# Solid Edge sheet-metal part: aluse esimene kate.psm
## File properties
Title: aluse esimene kate
Author: Stella-Marii
Template: Iso Metric Sheet Metal.psm
Last saved by: Stella-Marii
Revision: 15
Application: Solid Edge
Document Number: 11
Density: 7833,000 kg/m^3
Accuracy: 0,990
Material Thickness: 3,00 mm
Bend Radius: 1,00 mm
Relief Width: 1,00 mm
Relief Length: 0,00 mm
Neutral Factor: 0,330
Minimum Arc Length: 0,10 mm
Deviational Tolerance: 0,10 mm
Username: Stella-Marii
Material: Steel, structural
Face Style: Steel
Fill Style: ANSI32(Steel)
Virtual Style: Brushed steel
Grouping: Metals\Steel
LibraryName: Materials
Coef. of Thermal Exp: 1.3e-05
Thermal Conductivity: 32.0
Specific Heat: 481.0
Modulus of Elasticity: 199947953000.0
Poisson's Ratio: 0.29
Yield Stress: 262000766.0
Ultimate Stress: 358527364.0
Elongation: 0.0
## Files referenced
..\scooter.asm
@C:\Users\Stella-Marii\DATA\KOOL\Solid Edge - scooter\scooter.asm
C:\Users\Stella-Marii\DATA\KOOL\Solid Edge - scooter\raami alumine toru.par
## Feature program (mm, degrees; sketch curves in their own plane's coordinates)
base tab "unnamed BaseTab 1"
break corner "BreakCorner_1"  SetBackValue1 = 40 mm
sheet metal cutout "SheetMetalCutout_1"
bead "Bead_1"
louver "Louver_1"  LouverDepth = 10 mm; LouverHeight = 6.9579 mm
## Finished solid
Body 1: solid body, 90 faces, 206 edges, 126 vertices.
  Faces by surface: plane 32, cylinder 20, cone 16, torus 16, sphere 4, swept 2
  Edges by curve: line 104, circle 98, ellipse 4
Bounding box of the edges (mm; curved faces can reach further): 300.000 x 499.336 x 9.958, from (-150, -399.3361, 0) to (150, 100, 9.9579).
Cylindrical faces by radius (mm): R3 x16, R7.665 x1, R10.665 x1, R40 x2
Conical faces (half-angle, radius in mm at the cone's reference point): 15 deg R0.9042 x4, 15 deg R1.909 x4, 15 deg R3.802 x4, 15 deg R4.8068 x4
Toroidal faces (ring radius, tube radius in mm): R1.5 r3 x8, R4.8068 r3 x8
Spherical faces by radius (mm): R7.665 x2, R10.665 x2
Planar faces by outward normal: +x 1, +y 2, +z 5, -x 1, -y 2, -z 5, oblique 16
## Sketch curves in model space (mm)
circle centre (0, 30.2508, -28.3082) radius 23
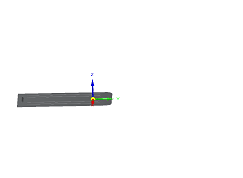
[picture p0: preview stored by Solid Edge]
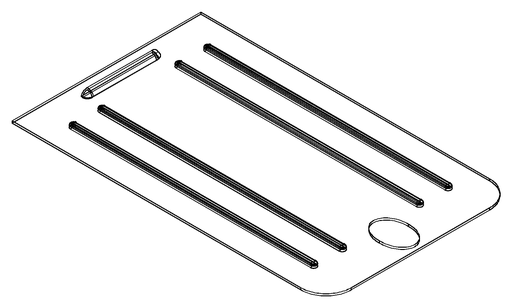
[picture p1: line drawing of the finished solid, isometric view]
